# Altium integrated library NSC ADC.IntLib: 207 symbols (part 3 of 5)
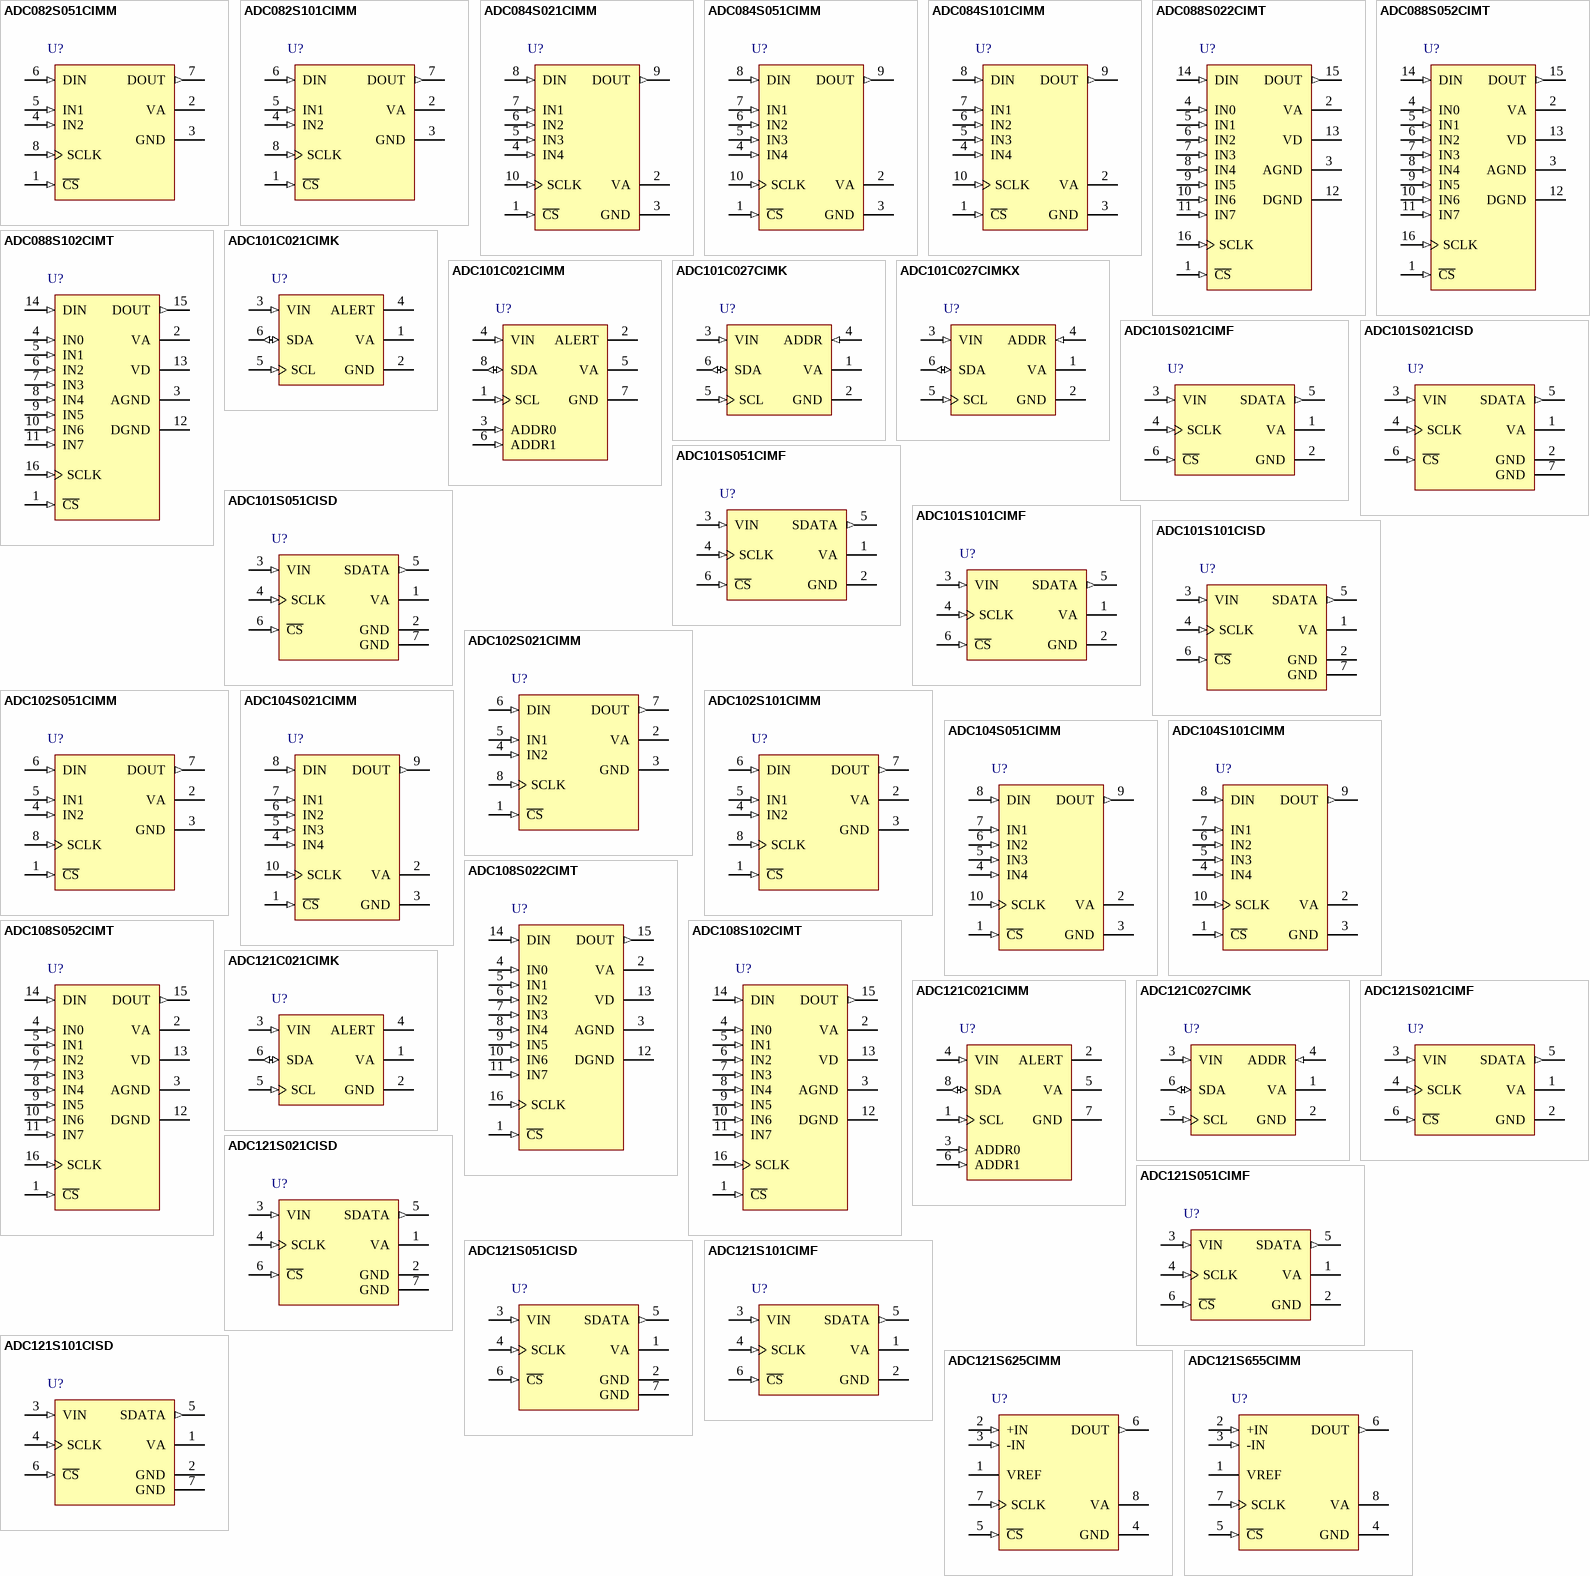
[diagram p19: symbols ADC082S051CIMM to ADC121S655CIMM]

## ADC088S022CIMT
designator U?
8-Channel, 50 kSPS to 200 kSPS, 8-Bit A/D Converter; PartNumber: ADC088S022CIMT; Manufacturer: National Semiconductor; CompType: ADC IC; PackageTopMarking: NSUZXYTT*88S022*CIMT; PowerWise: Y
footprint MTC16_N (TSOP, 16-Leads, Body 5x4.4mm, Pitch 0.65mm, IPC Medium Density)
footprint MTC16_L (TSOP, 16-Leads, Body 5x4.4mm, Pitch 0.65mm, IPC High Density)
footprint MTC16_M (TSOP, 16-Leads, Body 5x4.4mm, Pitch 0.65mm, IPC Low Density)
pins: 1 ~{CS} (in), 2 VA (power), 3 AGND (power), 4 IN0 (in), 5 IN1 (in), 6 IN2 (in), 7 IN3 (in), 8 IN4 (in), 9 IN5 (in), 10 IN6 (in), 11 IN7 (in), 12 DGND (power), 13 VD (power), 14 DIN (in), 15 DOUT (out), 16 SCLK (in)

## ADC088S052CIMT
designator U?
8-Channel, 200 kSPS to 500 kSPS, 8-Bit A/D Converter; PartNumber: ADC088S052CIMT; Manufacturer: National Semiconductor; CompType: ADC IC; PackageTopMarking: NSUZXYTT*088S052*CIMT; PowerWise: Y
footprint MTC16_N (TSOP, 16-Leads, Body 5x4.4mm, Pitch 0.65mm, IPC Medium Density)
footprint MTC16_L (TSOP, 16-Leads, Body 5x4.4mm, Pitch 0.65mm, IPC High Density)
footprint MTC16_M (TSOP, 16-Leads, Body 5x4.4mm, Pitch 0.65mm, IPC Low Density)
pins: 1 ~{CS} (in), 2 VA (power), 3 AGND (power), 4 IN0 (in), 5 IN1 (in), 6 IN2 (in), 7 IN3 (in), 8 IN4 (in), 9 IN5 (in), 10 IN6 (in), 11 IN7 (in), 12 DGND (power), 13 VD (power), 14 DIN (in), 15 DOUT (out), 16 SCLK (in)

## ADC088S102CIMT
designator U?
8-Channel, 500 kSPS to 1 MSPS, 8-Bit A/D Converter; PartNumber: ADC088S102CIMT; Manufacturer: National Semiconductor; CompType: ADC IC; PackageTopMarking: NSUZXYTT*088S102*CIMT; PowerWise: Y
footprint MTC16_N (TSOP, 16-Leads, Body 5x4.4mm, Pitch 0.65mm, IPC Medium Density)
footprint MTC16_L (TSOP, 16-Leads, Body 5x4.4mm, Pitch 0.65mm, IPC High Density)
footprint MTC16_M (TSOP, 16-Leads, Body 5x4.4mm, Pitch 0.65mm, IPC Low Density)
pins: 1 ~{CS} (in), 2 VA (power), 3 AGND (power), 4 IN0 (in), 5 IN1 (in), 6 IN2 (in), 7 IN3 (in), 8 IN4 (in), 9 IN5 (in), 10 IN6 (in), 11 IN7 (in), 12 DGND (power), 13 VD (power), 14 DIN (in), 15 DOUT (out), 16 SCLK (in)

## ADC101C021CIMK
designator U?
I2C-Compatible, 10-Bit Analog-to-Digital Converter (ADC) with Alert Pin; PartNumber: ADC101C021CIMK; Manufacturer: National Semiconductor; CompType: ADC IC; PackageTopMarking: X33C*XTT; PowerWise: N
footprint MK06A_N (SOT23, 6-Leads, Body 3.0x1.7mm, Pitch 0.95mm, Lead Span 2.9mm, IPC Medium Density)
footprint MK06A_L (SOT23, 6-Leads, Body 3.0x1.7mm, Pitch 0.95mm, Lead Span 2.9mm, IPC High Density)
footprint MK06A_M (SOT23, 6-Leads, Body 3.0x1.7mm, Pitch 0.95mm, Lead Span 2.9mm, IPC Low Density)
pins: 1 VA (power), 2 GND (power), 3 VIN (in), 4 ALERT (oc), 5 SCL (in), 6 SDA (io)

## ADC101C021CIMM
designator U?
I2C-Compatible, 10-Bit Analog-to-Digital Converter (ADC) with Alert Pin; PartNumber: ADC101C021CIMM; Manufacturer: National Semiconductor; CompType: ADC IC; PackageTopMarking: ZXTT*X38C; PowerWise: N
footprint MUA08A_N (TSOP, 8-Leads, Body 3x3mm, Pitch 0.65mm, IPC Medium Density)
footprint MUA08A_L (TSOP, 8-Leads, Body 3x3mm, Pitch 0.65mm, IPC High Density)
footprint MUA08A_M (TSOP, 8-Leads, Body 3x3mm, Pitch 0.65mm, IPC Low Density)
pins: 1 SCL (in), 2 ALERT (oc), 3 ADDR0 (in), 4 VIN (in), 5 VA (power), 6 ADDR1 (in), 7 GND (power), 8 SDA (io)

## ADC101C027CIMK
designator U?
I2C-Compatible, 10-Bit Analog-to-Digital Converter (ADC) with Alert Function; PartNumber: ADC101C027CIMK; Manufacturer: National Semiconductor; CompType: ADC IC; PackageTopMarking: X32C*XTT; PowerWise: N
footprint MK06A_N (SOT23, 6-Leads, Body 3.0x1.7mm, Pitch 0.95mm, Lead Span 2.9mm, IPC Medium Density)
footprint MK06A_L (SOT23, 6-Leads, Body 3.0x1.7mm, Pitch 0.95mm, Lead Span 2.9mm, IPC High Density)
footprint MK06A_M (SOT23, 6-Leads, Body 3.0x1.7mm, Pitch 0.95mm, Lead Span 2.9mm, IPC Low Density)
pins: 1 VA (power), 2 GND (power), 3 VIN (in), 4 ADDR (in), 5 SCL (in), 6 SDA (io)

## ADC101C027CIMKX
designator U?
I2C-Compatible, 10-Bit Analog-to-Digital Converter (ADC) with Alert Function; PartNumber: ADC101C027CIMKX; Manufacturer: National Semiconductor; CompType: ADC IC; PackageTopMarking: X31C*XTT
footprint MK06A_N (SOT23, 6-Leads, Body 3.0x1.7mm, Pitch 0.95mm, Lead Span 2.9mm, IPC Medium Density)
footprint MK06A_L (SOT23, 6-Leads, Body 3.0x1.7mm, Pitch 0.95mm, Lead Span 2.9mm, IPC High Density)
footprint MK06A_M (SOT23, 6-Leads, Body 3.0x1.7mm, Pitch 0.95mm, Lead Span 2.9mm, IPC Low Density)
pins: 1 VA (power), 2 GND (power), 3 VIN (in), 4 ADDR (in), 5 SCL (in), 6 SDA (io)

## ADC101S021CIMF
designator U?
Single Channel, 50 to 200 ksps, 10-Bit A/D Converter; PartNumber: ADC101S021CIMF; Manufacturer: National Semiconductor; CompType: ADC IC; PackageTopMarking: X08C*XTT; PowerWise: Y
footprint MF06A_N (SOT23, 6-Leads, Body 2.9x1.6mm, Pitch 0.95mm, Lead Span 2.8mm, IPC Medium Density)
footprint MF06A_L (SOT23, 6-Leads, Body 2.9x1.6mm, Pitch 0.95mm, Lead Span 2.8mm, IPC High Density)
footprint MF06A_M (SOT23, 6-Leads, Body 2.9x1.6mm, Pitch 0.95mm, Lead Span 2.8mm, IPC Low Density)
pins: 1 VA (power), 2 GND (power), 3 VIN (in), 4 SCLK (in), 5 SDATA (out), 6 ~{CS} (in)

## ADC101S021CISD
designator U?
Single Channel, 50 to 200 ksps, 10-Bit A/D Converter; PartNumber: ADC101S021CISD; Manufacturer: National Semiconductor; CompType: ADC IC; PackageTopMarking: XTT*X8C; PowerWise: Y
footprint SDB06A (SON, 6-Leads, Body 2.2x2.5mm, Pitch 0.65mm, NSC Recommended (SC-70 Land))
pins: 1 VA (power), 2 GND (power), 3 VIN (in), 4 SCLK (in), 5 SDATA (out), 6 ~{CS} (in), 7 GND (power)

## ADC101S051CIMF
designator U?
Single Channel, 200 to 500 ksps, 10-Bit A/D Converter; PartNumber: ADC101S051CIMF; Manufacturer: National Semiconductor; CompType: ADC IC; PackageTopMarking: X14C*XTT; PowerWise: Y
footprint MF06A_N (SOT23, 6-Leads, Body 2.9x1.6mm, Pitch 0.95mm, Lead Span 2.8mm, IPC Medium Density)
footprint MF06A_L (SOT23, 6-Leads, Body 2.9x1.6mm, Pitch 0.95mm, Lead Span 2.8mm, IPC High Density)
footprint MF06A_M (SOT23, 6-Leads, Body 2.9x1.6mm, Pitch 0.95mm, Lead Span 2.8mm, IPC Low Density)
pins: 1 VA (power), 2 GND (power), 3 VIN (in), 4 SCLK (in), 5 SDATA (out), 6 ~{CS} (in)

## ADC101S051CISD
designator U?
Single Channel, 200 to 500 ksps, 10-Bit A/D Converter; PartNumber: ADC101S051CISD; Manufacturer: National Semiconductor; CompType: ADC IC; PackageTopMarking: XTT*X5C; PowerWise: Y
footprint SDB06A (SON, 6-Leads, Body 2.2x2.5mm, Pitch 0.65mm, NSC Recommended (SC-70 Land))
pins: 1 VA (power), 2 GND (power), 3 VIN (in), 4 SCLK (in), 5 SDATA (out), 6 ~{CS} (in), 7 GND (power)

## ADC101S101CIMF
designator U?
1MSPS, 10-Bit A/D Converter in SOT-23; PartNumber: ADC101S101CIMF; Manufacturer: National Semiconductor; CompType: ADC IC; PackageTopMarking: X02C*XTT; PowerWise: Y
footprint MF06A_N (SOT23, 6-Leads, Body 2.9x1.6mm, Pitch 0.95mm, Lead Span 2.8mm, IPC Medium Density)
footprint MF06A_L (SOT23, 6-Leads, Body 2.9x1.6mm, Pitch 0.95mm, Lead Span 2.8mm, IPC High Density)
footprint MF06A_M (SOT23, 6-Leads, Body 2.9x1.6mm, Pitch 0.95mm, Lead Span 2.8mm, IPC Low Density)
pins: 1 VA (power), 2 GND (power), 3 VIN (in), 4 SCLK (in), 5 SDATA (out), 6 ~{CS} (in)

## ADC101S101CISD
designator U?
1MSPS, 10-Bit A/D Converter in SOT-23; PartNumber: ADC101S101CISD; Manufacturer: National Semiconductor; CompType: ADC IC; PackageTopMarking: XTT*X2C; PowerWise: Y
footprint SDB06A (SON, 6-Leads, Body 2.2x2.5mm, Pitch 0.65mm, NSC Recommended (SC-70 Land))
pins: 1 VA (power), 2 GND (power), 3 VIN (in), 4 SCLK (in), 5 SDATA (out), 6 ~{CS} (in), 7 GND (power)

## ADC102S021CIMM
designator U?
2 Channel, 200 KSPS, 10-Bit A/D Converter; PartNumber: ADC102S021CIMM; Manufacturer: National Semiconductor; CompType: ADC IC; PackageTopMarking: ZXTT*X17C; PowerWise: Y
footprint MUA08A_N (TSOP, 8-Leads, Body 3x3mm, Pitch 0.65mm, IPC Medium Density)
footprint MUA08A_L (TSOP, 8-Leads, Body 3x3mm, Pitch 0.65mm, IPC High Density)
footprint MUA08A_M (TSOP, 8-Leads, Body 3x3mm, Pitch 0.65mm, IPC Low Density)
pins: 1 ~{CS} (in), 2 VA (power), 3 GND (power), 4 IN2 (in), 5 IN1 (in), 6 DIN (in), 7 DOUT (out), 8 SCLK (in)

## ADC102S051CIMM
designator U?
2 Channel, 500 kSPS, 10-Bit A/D Converter; PartNumber: ADC102S051CIMM; Manufacturer: National Semiconductor; CompType: ADC IC; PackageTopMarking: ZXTT*X05C; PowerWise: Y
footprint MUA08A_N (TSOP, 8-Leads, Body 3x3mm, Pitch 0.65mm, IPC Medium Density)
footprint MUA08A_L (TSOP, 8-Leads, Body 3x3mm, Pitch 0.65mm, IPC High Density)
footprint MUA08A_M (TSOP, 8-Leads, Body 3x3mm, Pitch 0.65mm, IPC Low Density)
pins: 1 ~{CS} (in), 2 VA (power), 3 GND (power), 4 IN2 (in), 5 IN1 (in), 6 DIN (in), 7 DOUT (out), 8 SCLK (in)

## ADC102S101CIMM
designator U?
2 Channel, 1 MSPS, 10-Bit A/D Converter; PartNumber: ADC102S101CIMM; Manufacturer: National Semiconductor; CompType: ADC IC; PackageTopMarking: ZXTT*X23C; PowerWise: Y
footprint MUA08A_N (TSOP, 8-Leads, Body 3x3mm, Pitch 0.65mm, IPC Medium Density)
footprint MUA08A_L (TSOP, 8-Leads, Body 3x3mm, Pitch 0.65mm, IPC High Density)
footprint MUA08A_M (TSOP, 8-Leads, Body 3x3mm, Pitch 0.65mm, IPC Low Density)
pins: 1 ~{CS} (in), 2 VA (power), 3 GND (power), 4 IN2 (in), 5 IN1 (in), 6 DIN (in), 7 DOUT (out), 8 SCLK (in)

## ADC104S021CIMM
designator U?
4 Channel 200 kSPS, 10-Bit A/D Converter; PartNumber: ADC104S021CIMM; Manufacturer: National Semiconductor; CompType: ADC IC; PackageTopMarking: ZXTT*X20C; PowerWise: Y
footprint MUB10A_N (TSSOP, 10-Leads, Body 3x3mm, Pitch 0.5mm, IPC Medium Density)
footprint MUB10A_L (TSSOP, 10-Leads, Body 3x3mm, Pitch 0.5mm, IPC High Density)
footprint MUB10A_M (TSSOP, 10-Leads, Body 3x3mm, Pitch 0.5mm, IPC Low Density)
pins: 1 ~{CS} (in), 2 VA (power), 3 GND (power), 4 IN4 (in), 5 IN3 (in), 6 IN2 (in), 7 IN1 (in), 8 DIN (in), 9 DOUT (out), 10 SCLK (in)

## ADC104S051CIMM
designator U?
4 Channel 500 kSPS, 10-Bit A/D Converter; PartNumber: ADC104S051CIMM; Manufacturer: National Semiconductor; CompType: ADC IC; PackageTopMarking: ZXTT*X11C; PowerWise: Y
footprint MUB10A_N (TSSOP, 10-Leads, Body 3x3mm, Pitch 0.5mm, IPC Medium Density)
footprint MUB10A_L (TSSOP, 10-Leads, Body 3x3mm, Pitch 0.5mm, IPC High Density)
footprint MUB10A_M (TSSOP, 10-Leads, Body 3x3mm, Pitch 0.5mm, IPC Low Density)
pins: 1 ~{CS} (in), 2 VA (power), 3 GND (power), 4 IN4 (in), 5 IN3 (in), 6 IN2 (in), 7 IN1 (in), 8 DIN (in), 9 DOUT (out), 10 SCLK (in)

## ADC104S101CIMM
designator U?
4 Channel 1 MSPS, 10-Bit A/D Converter; PartNumber: ADC104S101CIMM; Manufacturer: National Semiconductor; CompType: ADC IC; PackageTopMarking: ZXTT*X26C; PowerWise: Y
footprint MUB10A_N (TSSOP, 10-Leads, Body 3x3mm, Pitch 0.5mm, IPC Medium Density)
footprint MUB10A_L (TSSOP, 10-Leads, Body 3x3mm, Pitch 0.5mm, IPC High Density)
footprint MUB10A_M (TSSOP, 10-Leads, Body 3x3mm, Pitch 0.5mm, IPC Low Density)
pins: 1 ~{CS} (in), 2 VA (power), 3 GND (power), 4 IN4 (in), 5 IN3 (in), 6 IN2 (in), 7 IN1 (in), 8 DIN (in), 9 DOUT (out), 10 SCLK (in)

## ADC108S022CIMT
designator U?
8-Channel, 50 kSPS to 200 kSPS, 10-Bit A/D Converter; PartNumber: ADC108S022CIMT; Manufacturer: National Semiconductor; CompType: ADC IC; PackageTopMarking: NSUZXYTT*108S022*CIMT; PowerWise: Y
footprint MTC16_N (TSOP, 16-Leads, Body 5x4.4mm, Pitch 0.65mm, IPC Medium Density)
footprint MTC16_L (TSOP, 16-Leads, Body 5x4.4mm, Pitch 0.65mm, IPC High Density)
footprint MTC16_M (TSOP, 16-Leads, Body 5x4.4mm, Pitch 0.65mm, IPC Low Density)
pins: 1 ~{CS} (in), 2 VA (power), 3 AGND (power), 4 IN0 (in), 5 IN1 (in), 6 IN2 (in), 7 IN3 (in), 8 IN4 (in), 9 IN5 (in), 10 IN6 (in), 11 IN7 (in), 12 DGND (power), 13 VD (power), 14 DIN (in), 15 DOUT (out), 16 SCLK (in)

## ADC108S052CIMT
designator U?
8-Channel, 200 kSPS to 500 kSPS, 10-Bit A/D Converter; PartNumber: ADC108S052CIMT; Manufacturer: National Semiconductor; CompType: ADC IC; PackageTopMarking: NSUZXYTT*108S052*CIMT; PowerWise: Y
footprint MTC16_N (TSOP, 16-Leads, Body 5x4.4mm, Pitch 0.65mm, IPC Medium Density)
footprint MTC16_L (TSOP, 16-Leads, Body 5x4.4mm, Pitch 0.65mm, IPC High Density)
footprint MTC16_M (TSOP, 16-Leads, Body 5x4.4mm, Pitch 0.65mm, IPC Low Density)
pins: 1 ~{CS} (in), 2 VA (power), 3 AGND (power), 4 IN0 (in), 5 IN1 (in), 6 IN2 (in), 7 IN3 (in), 8 IN4 (in), 9 IN5 (in), 10 IN6 (in), 11 IN7 (in), 12 DGND (power), 13 VD (power), 14 DIN (in), 15 DOUT (out), 16 SCLK (in)

## ADC108S102CIMT
designator U?
8-Channel, 500 kSPS to 1 MSPS, 10-Bit A/D Converter; PartNumber: ADC108S102CIMT; Manufacturer: National Semiconductor; CompType: ADC IC; PackageTopMarking: NSUZXYTT*108S102*CIMT; PowerWise: Y
footprint MTC16_N (TSOP, 16-Leads, Body 5x4.4mm, Pitch 0.65mm, IPC Medium Density)
footprint MTC16_L (TSOP, 16-Leads, Body 5x4.4mm, Pitch 0.65mm, IPC High Density)
footprint MTC16_M (TSOP, 16-Leads, Body 5x4.4mm, Pitch 0.65mm, IPC Low Density)
pins: 1 ~{CS} (in), 2 VA (power), 3 AGND (power), 4 IN0 (in), 5 IN1 (in), 6 IN2 (in), 7 IN3 (in), 8 IN4 (in), 9 IN5 (in), 10 IN6 (in), 11 IN7 (in), 12 DGND (power), 13 VD (power), 14 DIN (in), 15 DOUT (out), 16 SCLK (in)

## ADC121C021CIMK
designator U?
I2C-Compatible, 12-Bit Analog-to-Digital Converter (ADC) with Alert Pin; PartNumber: ADC121C021CIMK; Manufacturer: National Semiconductor; CompType: ADC IC; PackageTopMarking: X30C*XTT; PowerWise: Y
footprint MK06A_N (SOT23, 6-Leads, Body 3.0x1.7mm, Pitch 0.95mm, Lead Span 2.9mm, IPC Medium Density)
footprint MK06A_L (SOT23, 6-Leads, Body 3.0x1.7mm, Pitch 0.95mm, Lead Span 2.9mm, IPC High Density)
footprint MK06A_M (SOT23, 6-Leads, Body 3.0x1.7mm, Pitch 0.95mm, Lead Span 2.9mm, IPC Low Density)
pins: 1 VA (power), 2 GND (power), 3 VIN (in), 4 ALERT (oc), 5 SCL (in), 6 SDA (io)

## ADC121C021CIMM
designator U?
I2C-Compatible, 12-Bit Analog-to-Digital Converter with Alert Pin; PartNumber: ADC121C021CIMM; Manufacturer: National Semiconductor; CompType: ADC IC; PackageTopMarking: ZXTT*X37C; PowerWise: Y
footprint MUA08A_N (TSOP, 8-Leads, Body 3x3mm, Pitch 0.65mm, IPC Medium Density)
footprint MUA08A_L (TSOP, 8-Leads, Body 3x3mm, Pitch 0.65mm, IPC High Density)
footprint MUA08A_M (TSOP, 8-Leads, Body 3x3mm, Pitch 0.65mm, IPC Low Density)
pins: 1 SCL (in), 2 ALERT (oc), 3 ADDR0 (in), 4 VIN (in), 5 VA (power), 6 ADDR1 (in), 7 GND (power), 8 SDA (io)

## ADC121C027CIMK
designator U?
I2C-Compatible, 12-Bit Analog-to-Digital Converter with Alert Function; PartNumber: ADC121C027CIMK; Manufacturer: National Semiconductor; CompType: ADC IC; PackageTopMarking: X31C*XTT; PowerWise: Y
footprint MK06A_N (SOT23, 6-Leads, Body 3.0x1.7mm, Pitch 0.95mm, Lead Span 2.9mm, IPC Medium Density)
footprint MK06A_L (SOT23, 6-Leads, Body 3.0x1.7mm, Pitch 0.95mm, Lead Span 2.9mm, IPC High Density)
footprint MK06A_M (SOT23, 6-Leads, Body 3.0x1.7mm, Pitch 0.95mm, Lead Span 2.9mm, IPC Low Density)
pins: 1 VA (power), 2 GND (power), 3 VIN (in), 4 ADDR (in), 5 SCL (in), 6 SDA (io)

## ADC121S021CIMF
designator U?
Single Channel, 50 to 200 ksps, 12-Bit A/D Converter; PartNumber: ADC121S021CIMF; Manufacturer: National Semiconductor; CompType: ADC IC; PackageTopMarking: X07C*XTT; PowerWise: Y
footprint MF06A_N (SOT23, 6-Leads, Body 2.9x1.6mm, Pitch 0.95mm, Lead Span 2.8mm, IPC Medium Density)
footprint MF06A_L (SOT23, 6-Leads, Body 2.9x1.6mm, Pitch 0.95mm, Lead Span 2.8mm, IPC High Density)
footprint MF06A_M (SOT23, 6-Leads, Body 2.9x1.6mm, Pitch 0.95mm, Lead Span 2.8mm, IPC Low Density)
pins: 1 VA (power), 2 GND (power), 3 VIN (in), 4 SCLK (in), 5 SDATA (out), 6 ~{CS} (in)

## ADC121S021CISD
designator U?
Single Channel, 50 to 200 ksps, 12-Bit A/D Converter; PartNumber: ADC121S021CISD; Manufacturer: National Semiconductor; CompType: ADC IC; PackageTopMarking: XTT*X7C; PowerWise: Y
footprint SDB06A (SON, 6-Leads, Body 2.2x2.5mm, Pitch 0.65mm, NSC Recommended (SC-70 Land))
pins: 1 VA (power), 2 GND (power), 3 VIN (in), 4 SCLK (in), 5 SDATA (out), 6 ~{CS} (in), 7 GND (power)

## ADC121S051CIMF
designator U?
Single Channel, 200 to 500 ksps, 12-Bit A/D Converter; PartNumber: ADC121S051CIMF; Manufacturer: National Semiconductor; CompType: ADC IC; PackageTopMarking: X13C*XTT; PowerWise: Y
footprint MF06A_N (SOT23, 6-Leads, Body 2.9x1.6mm, Pitch 0.95mm, Lead Span 2.8mm, IPC Medium Density)
footprint MF06A_L (SOT23, 6-Leads, Body 2.9x1.6mm, Pitch 0.95mm, Lead Span 2.8mm, IPC High Density)
footprint MF06A_M (SOT23, 6-Leads, Body 2.9x1.6mm, Pitch 0.95mm, Lead Span 2.8mm, IPC Low Density)
pins: 1 VA (power), 2 GND (power), 3 VIN (in), 4 SCLK (in), 5 SDATA (out), 6 ~{CS} (in)

## ADC121S051CISD
designator U?
Single Channel, 200 to 500 ksps, 12-Bit A/D Converter; PartNumber: ADC121S051CISD; Manufacturer: National Semiconductor; CompType: ADC IC; PackageTopMarking: XTT*X4C; PowerWise: Y
footprint SDB06A (SON, 6-Leads, Body 2.2x2.5mm, Pitch 0.65mm, NSC Recommended (SC-70 Land))
pins: 1 VA (power), 2 GND (power), 3 VIN (in), 4 SCLK (in), 5 SDATA (out), 6 ~{CS} (in), 7 GND (power)

## ADC121S101CIMF
designator U?
1MSPS, 12-Bit A/D Converter in SOT-23; PartNumber: ADC121S101CIMF; Manufacturer: National Semiconductor; CompType: ADC IC; PackageTopMarking: X01C*XTT; PowerWise: Y
footprint MF06A_N (SOT23, 6-Leads, Body 2.9x1.6mm, Pitch 0.95mm, Lead Span 2.8mm, IPC Medium Density)
footprint MF06A_L (SOT23, 6-Leads, Body 2.9x1.6mm, Pitch 0.95mm, Lead Span 2.8mm, IPC High Density)
footprint MF06A_M (SOT23, 6-Leads, Body 2.9x1.6mm, Pitch 0.95mm, Lead Span 2.8mm, IPC Low Density)
pins: 1 VA (power), 2 GND (power), 3 VIN (in), 4 SCLK (in), 5 SDATA (out), 6 ~{CS} (in)

## ADC121S101CISD
designator U?
1MSPS, 12-Bit A/D Converter in SOT-23; PartNumber: ADC121S101CISD; Manufacturer: National Semiconductor; CompType: ADC IC; PackageTopMarking: XTT*X1C; PowerWise: Y
footprint SDB06A (SON, 6-Leads, Body 2.2x2.5mm, Pitch 0.65mm, NSC Recommended (SC-70 Land))
pins: 1 VA (power), 2 GND (power), 3 VIN (in), 4 SCLK (in), 5 SDATA (out), 6 ~{CS} (in), 7 GND (power)

## ADC121S625CIMM
designator U?
12-Bit, 50 ksps to 200 ksps, Differential Input, Micro Power Sampling A/D Converter; PartNumber: ADC121S625CIMM; Manufacturer: National Semiconductor; CompType: ADC IC; PackageTopMarking: ZXTT*X0AC; PowerWise: N
footprint MUA08A_N (TSOP, 8-Leads, Body 3x3mm, Pitch 0.65mm, IPC Medium Density)
footprint MUA08A_L (TSOP, 8-Leads, Body 3x3mm, Pitch 0.65mm, IPC High Density)
footprint MUA08A_M (TSOP, 8-Leads, Body 3x3mm, Pitch 0.65mm, IPC Low Density)
pins: 1 VREF (power), 2 +IN (in), 3 -IN (in), 4 GND (power), 5 ~{CS} (in), 6 DOUT (out), 7 SCLK (in), 8 VA (power)

## ADC121S655CIMM
designator U?
12-Bit, 200 kSPS to 500 kSPS, Differential Input, Micro Power A/D Converter; PartNumber: ADC121S655CIMM; Manufacturer: National Semiconductor; CompType: ADC IC; PackageTopMarking: ZXTT*X2AC; PowerWise: N
footprint MUA08A_N (TSOP, 8-Leads, Body 3x3mm, Pitch 0.65mm, IPC Medium Density)
footprint MUA08A_L (TSOP, 8-Leads, Body 3x3mm, Pitch 0.65mm, IPC High Density)
footprint MUA08A_M (TSOP, 8-Leads, Body 3x3mm, Pitch 0.65mm, IPC Low Density)
pins: 1 VREF (power), 2 +IN (in), 3 -IN (in), 4 GND (power), 5 ~{CS} (in), 6 DOUT (out), 7 SCLK (in), 8 VA (power)

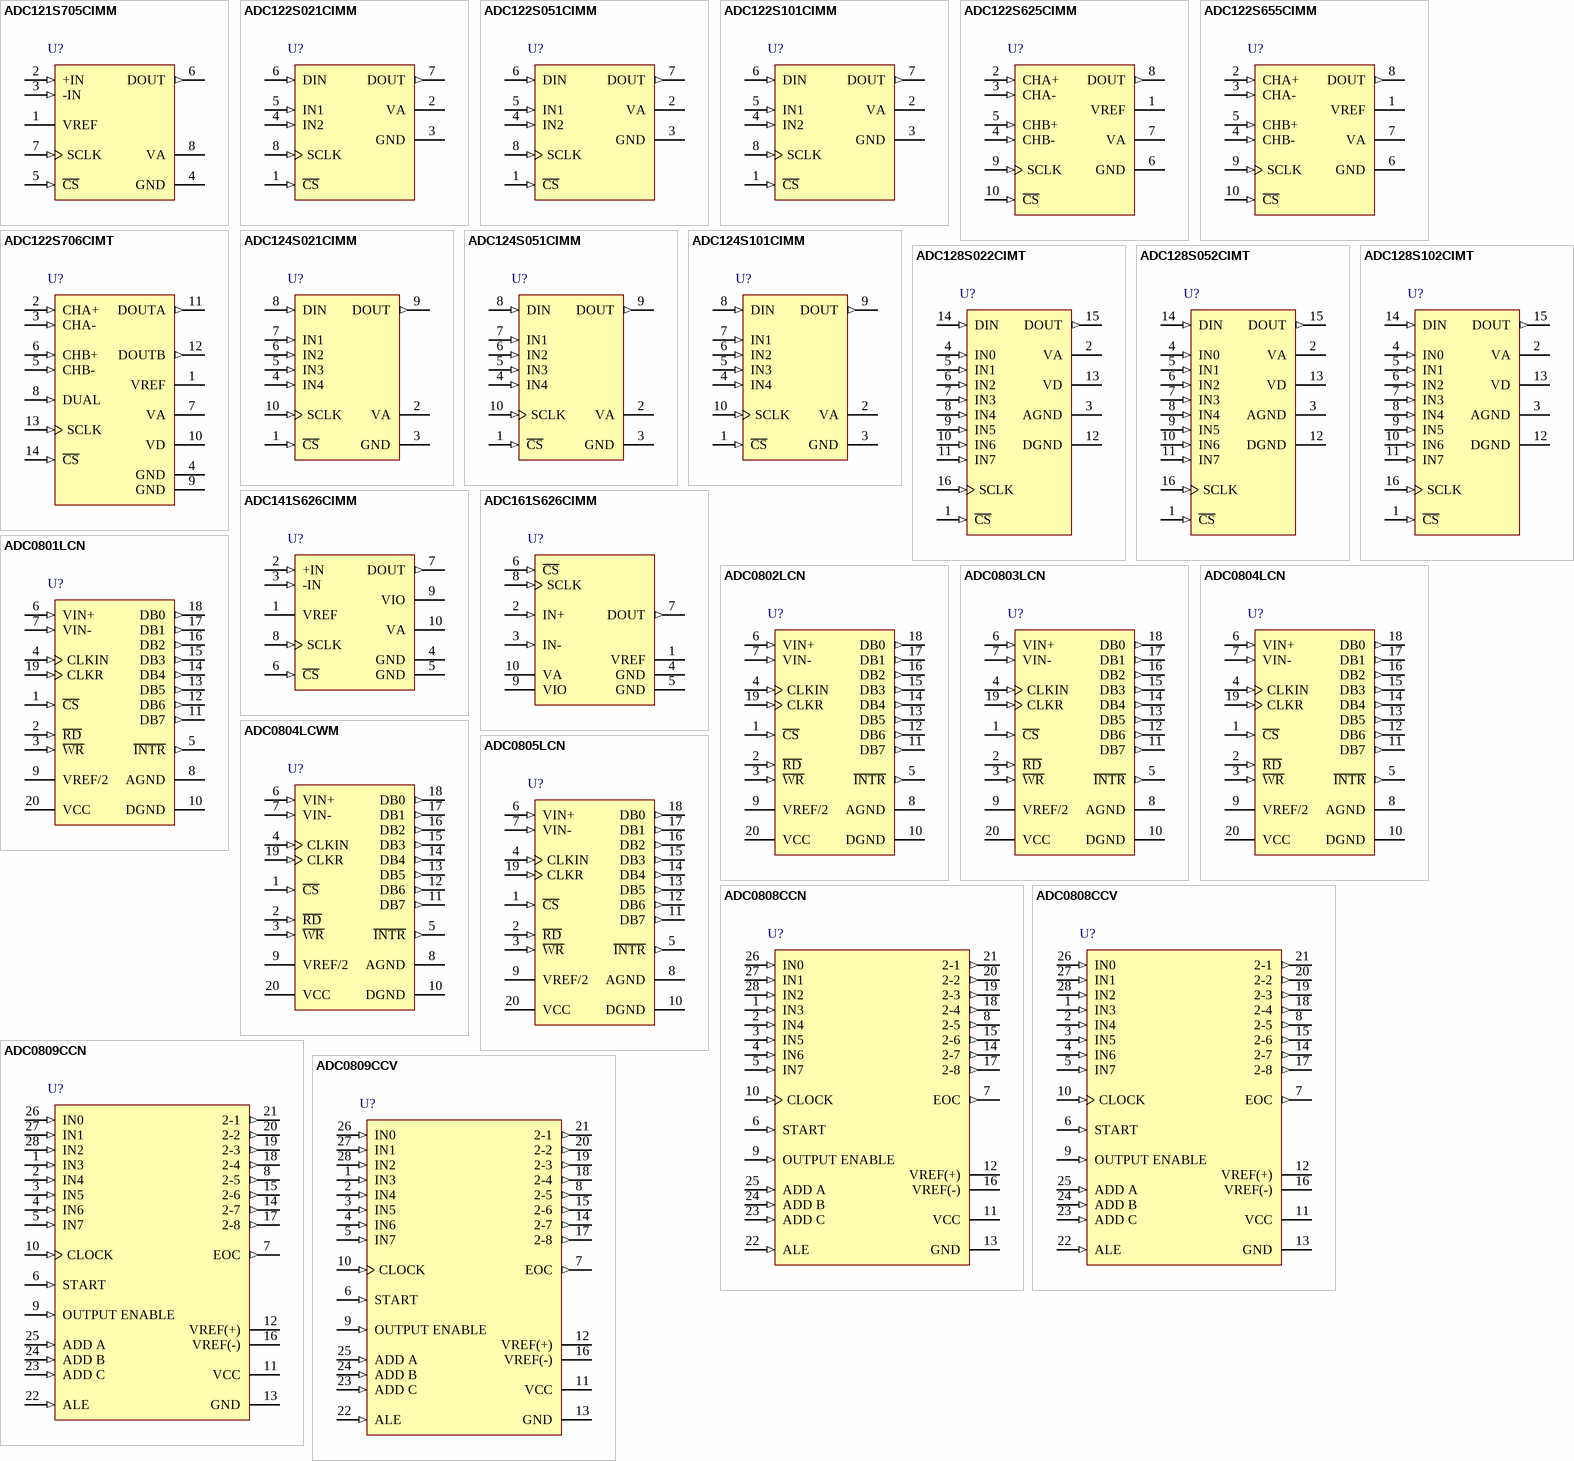
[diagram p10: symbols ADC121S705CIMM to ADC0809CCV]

## ADC121S705CIMM
designator U?
12-Bit, 500 kSPS to 1 MSPS, Differential Input, Micro Power A/D Converter; PartNumber: ADC121S705CIMM; Manufacturer: National Semiconductor; CompType: ADC IC; PackageTopMarking: ZXTT*X1AC; PowerWise: N
footprint MUA08A_N (TSOP, 8-Leads, Body 3x3mm, Pitch 0.65mm, IPC Medium Density)
footprint MUA08A_L (TSOP, 8-Leads, Body 3x3mm, Pitch 0.65mm, IPC High Density)
footprint MUA08A_M (TSOP, 8-Leads, Body 3x3mm, Pitch 0.65mm, IPC Low Density)
pins: 1 VREF (power), 2 +IN (in), 3 -IN (in), 4 GND (power), 5 ~{CS} (in), 6 DOUT (out), 7 SCLK (in), 8 VA (power)

## ADC122S021CIMM
designator U?
2 Channel, 200 KSPS 12-Bit A/D Converter; PartNumber: ADC122S021CIMM; Manufacturer: National Semiconductor; CompType: ADC IC; PackageTopMarking: ZXTT*X18C; PowerWise: Y
footprint MUA08A_N (TSOP, 8-Leads, Body 3x3mm, Pitch 0.65mm, IPC Medium Density)
footprint MUA08A_L (TSOP, 8-Leads, Body 3x3mm, Pitch 0.65mm, IPC High Density)
footprint MUA08A_M (TSOP, 8-Leads, Body 3x3mm, Pitch 0.65mm, IPC Low Density)
pins: 1 ~{CS} (in), 2 VA (power), 3 GND (power), 4 IN2 (in), 5 IN1 (in), 6 DIN (in), 7 DOUT (out), 8 SCLK (in)

## ADC122S051CIMM
designator U?
2 Channel, 500 kSPS 12-Bit A/D Converter; PartNumber: ADC122S051CIMM; Manufacturer: National Semiconductor; CompType: ADC IC; PackageTopMarking: ZXTT*X06C; PowerWise: Y
footprint MUA08A_N (TSOP, 8-Leads, Body 3x3mm, Pitch 0.65mm, IPC Medium Density)
footprint MUA08A_L (TSOP, 8-Leads, Body 3x3mm, Pitch 0.65mm, IPC High Density)
footprint MUA08A_M (TSOP, 8-Leads, Body 3x3mm, Pitch 0.65mm, IPC Low Density)
pins: 1 ~{CS} (in), 2 VA (power), 3 GND (power), 4 IN2 (in), 5 IN1 (in), 6 DIN (in), 7 DOUT (out), 8 SCLK (in)

## ADC122S101CIMM
designator U?
2 Channel, 1MSPS 12-Bit A/D Converter; PartNumber: ADC122S101CIMM; Manufacturer: National Semiconductor; CompType: ADC IC; PackageTopMarking: ZXTT*X24C; PowerWise: Y
footprint MUA08A_N (TSOP, 8-Leads, Body 3x3mm, Pitch 0.65mm, IPC Medium Density)
footprint MUA08A_L (TSOP, 8-Leads, Body 3x3mm, Pitch 0.65mm, IPC High Density)
footprint MUA08A_M (TSOP, 8-Leads, Body 3x3mm, Pitch 0.65mm, IPC Low Density)
pins: 1 ~{CS} (in), 2 VA (power), 3 GND (power), 4 IN2 (in), 5 IN1 (in), 6 DIN (in), 7 DOUT (out), 8 SCLK (in)

## ADC122S625CIMM
designator U?
Dual 12-Bit, 50 kSPS to 200 kSPS, Simultaneous Sampling A/D Converter; PartNumber: ADC122S625CIMM; Manufacturer: National Semiconductor; CompType: ADC IC; PackageTopMarking: ZXTT*X35C; PowerWise: N
footprint MUB10A_N (TSSOP, 10-Leads, Body 3x3mm, Pitch 0.5mm, IPC Medium Density)
footprint MUB10A_L (TSSOP, 10-Leads, Body 3x3mm, Pitch 0.5mm, IPC High Density)
footprint MUB10A_M (TSSOP, 10-Leads, Body 3x3mm, Pitch 0.5mm, IPC Low Density)
pins: 1 VREF (power), 2 CHA+ (in), 3 CHA- (in), 4 CHB- (in), 5 CHB+ (in), 6 GND (power), 7 VA (power), 8 DOUT (out), 9 SCLK (in), 10 ~{CS} (in)

## ADC122S655CIMM
designator U?
Dual 12-Bit, 200 kSPS to 500 kSPS, Simultaneous Sampling A/D Converter; PartNumber: ADC122S655CIMM; Manufacturer: National Semiconductor; CompType: ADC IC; PackageTopMarking: ZXTT*X96C; PowerWise: N
footprint MUB10A_N (TSSOP, 10-Leads, Body 3x3mm, Pitch 0.5mm, IPC Medium Density)
footprint MUB10A_L (TSSOP, 10-Leads, Body 3x3mm, Pitch 0.5mm, IPC High Density)
footprint MUB10A_M (TSSOP, 10-Leads, Body 3x3mm, Pitch 0.5mm, IPC Low Density)
pins: 1 VREF (power), 2 CHA+ (in), 3 CHA- (in), 4 CHB- (in), 5 CHB+ (in), 6 GND (power), 7 VA (power), 8 DOUT (out), 9 SCLK (in), 10 ~{CS} (in)

## ADC122S706CIMT
designator U?
Dual 12-Bit, 500 kSPS to 1 MSPS, Simultaneous Sampling A/D Converter; PartNumber: ADC122S706CIMT; Manufacturer: National Semiconductor; CompType: ADC IC; PackageTopMarking: NSUZXYTT*2S706*CIMT; PowerWise: N
footprint MTC14_N (TSOP, 14-Leads, Body 5x4.4mm, Pitch 0.65mm, IPC Medium Density)
footprint MTC14_L (TSOP, 14-Leads, Body 5x4.4mm, Pitch 0.65mm, IPC High Density)
footprint MTC14_M (TSOP, 14-Leads, Body 5x4.4mm, Pitch 0.65mm, IPC Low Density)
pins: 1 VREF (power), 2 CHA+ (in), 3 CHA- (in), 4 GND (power), 5 CHB- (in), 6 CHB+ (in), 7 VA (power), 8 DUAL (in), 9 GND (power), 10 VD (power), 11 DOUTA (out), 12 DOUTB (out), 13 SCLK (in), 14 ~{CS} (in)

## ADC124S021CIMM
designator U?
4 Channel, 200 kSPS, 12-Bit A/D Converter; PartNumber: ADC124S021CIMM; Manufacturer: National Semiconductor; CompType: ADC IC; PackageTopMarking: ZXTT*X21C; PowerWise: Y
footprint MUB10A_N (TSSOP, 10-Leads, Body 3x3mm, Pitch 0.5mm, IPC Medium Density)
footprint MUB10A_L (TSSOP, 10-Leads, Body 3x3mm, Pitch 0.5mm, IPC High Density)
footprint MUB10A_M (TSSOP, 10-Leads, Body 3x3mm, Pitch 0.5mm, IPC Low Density)
pins: 1 ~{CS} (in), 2 VA (power), 3 GND (power), 4 IN4 (in), 5 IN3 (in), 6 IN2 (in), 7 IN1 (in), 8 DIN (in), 9 DOUT (out), 10 SCLK (in)

## ADC124S051CIMM
designator U?
4 Channel, 500 kSPS, 12-Bit A/D Converter; PartNumber: ADC124S051CIMM; Manufacturer: National Semiconductor; CompType: ADC IC; PackageTopMarking: ZXTT*X12C; PowerWise: Y
footprint MUB10A_N (TSSOP, 10-Leads, Body 3x3mm, Pitch 0.5mm, IPC Medium Density)
footprint MUB10A_L (TSSOP, 10-Leads, Body 3x3mm, Pitch 0.5mm, IPC High Density)
footprint MUB10A_M (TSSOP, 10-Leads, Body 3x3mm, Pitch 0.5mm, IPC Low Density)
pins: 1 ~{CS} (in), 2 VA (power), 3 GND (power), 4 IN4 (in), 5 IN3 (in), 6 IN2 (in), 7 IN1 (in), 8 DIN (in), 9 DOUT (out), 10 SCLK (in)

## ADC124S101CIMM
designator U?
4 Channel, 1 MSPS, 12-Bit A/D Converter; PartNumber: ADC124S101CIMM; Manufacturer: National Semiconductor; CompType: ADC IC; PackageTopMarking: ZXTT*X27C; PowerWise: Y
footprint MUB10A_N (TSSOP, 10-Leads, Body 3x3mm, Pitch 0.5mm, IPC Medium Density)
footprint MUB10A_L (TSSOP, 10-Leads, Body 3x3mm, Pitch 0.5mm, IPC High Density)
footprint MUB10A_M (TSSOP, 10-Leads, Body 3x3mm, Pitch 0.5mm, IPC Low Density)
pins: 1 ~{CS} (in), 2 VA (power), 3 GND (power), 4 IN4 (in), 5 IN3 (in), 6 IN2 (in), 7 IN1 (in), 8 DIN (in), 9 DOUT (out), 10 SCLK (in)

## ADC128S022CIMT
designator U?
8-Channel, 50 kSPS to 200 kSPS, 12-Bit A/D Converter; PartNumber: ADC128S022CIMT; Manufacturer: National Semiconductor; CompType: ADC IC; PackageTopMarking: NSUZXYTT*128S022*CIMT; PowerWise: Y
footprint MTC16_N (TSOP, 16-Leads, Body 5x4.4mm, Pitch 0.65mm, IPC Medium Density)
footprint MTC16_L (TSOP, 16-Leads, Body 5x4.4mm, Pitch 0.65mm, IPC High Density)
footprint MTC16_M (TSOP, 16-Leads, Body 5x4.4mm, Pitch 0.65mm, IPC Low Density)
pins: 1 ~{CS} (in), 2 VA (power), 3 AGND (power), 4 IN0 (in), 5 IN1 (in), 6 IN2 (in), 7 IN3 (in), 8 IN4 (in), 9 IN5 (in), 10 IN6 (in), 11 IN7 (in), 12 DGND (power), 13 VD (power), 14 DIN (in), 15 DOUT (out), 16 SCLK (in)

## ADC128S052CIMT
designator U?
8-Channel, 200 kSPS to 500 kSPS, 12-Bit A/D Converter; PartNumber: ADC128S052CIMT; Manufacturer: National Semiconductor; CompType: ADC IC; PackageTopMarking: NSUZXYTT*128S052*CIMT; PowerWise: Y
footprint MTC16_N (TSOP, 16-Leads, Body 5x4.4mm, Pitch 0.65mm, IPC Medium Density)
footprint MTC16_L (TSOP, 16-Leads, Body 5x4.4mm, Pitch 0.65mm, IPC High Density)
footprint MTC16_M (TSOP, 16-Leads, Body 5x4.4mm, Pitch 0.65mm, IPC Low Density)
pins: 1 ~{CS} (in), 2 VA (power), 3 AGND (power), 4 IN0 (in), 5 IN1 (in), 6 IN2 (in), 7 IN3 (in), 8 IN4 (in), 9 IN5 (in), 10 IN6 (in), 11 IN7 (in), 12 DGND (power), 13 VD (power), 14 DIN (in), 15 DOUT (out), 16 SCLK (in)

## ADC128S102CIMT
designator U?
8-Channel, 500 kSPS to 1 MSPS, 12-Bit A/D Converter; PartNumber: ADC128S102CIMT; Manufacturer: National Semiconductor; CompType: ADC IC; PackageTopMarking: NSUZXYTT*128S102*CIMT; PowerWise: Y
footprint MTC16_N (TSOP, 16-Leads, Body 5x4.4mm, Pitch 0.65mm, IPC Medium Density)
footprint MTC16_L (TSOP, 16-Leads, Body 5x4.4mm, Pitch 0.65mm, IPC High Density)
footprint MTC16_M (TSOP, 16-Leads, Body 5x4.4mm, Pitch 0.65mm, IPC Low Density)
pins: 1 ~{CS} (in), 2 VA (power), 3 AGND (power), 4 IN0 (in), 5 IN1 (in), 6 IN2 (in), 7 IN3 (in), 8 IN4 (in), 9 IN5 (in), 10 IN6 (in), 11 IN7 (in), 12 DGND (power), 13 VD (power), 14 DIN (in), 15 DOUT (out), 16 SCLK (in)

## ADC141S626CIMM
designator U?
14-Bit, 50 kSPS to 250 kSPS, Differential Input, Micro Power A/D Converter; PartNumber: ADC141S626CIMM; Manufacturer: National Semiconductor; CompType: ADC IC; PackageTopMarking: ZXTT*X94C; PowerWise: Y
footprint MUB10A_N (TSSOP, 10-Leads, Body 3x3mm, Pitch 0.5mm, IPC Medium Density)
footprint MUB10A_L (TSSOP, 10-Leads, Body 3x3mm, Pitch 0.5mm, IPC High Density)
footprint MUB10A_M (TSSOP, 10-Leads, Body 3x3mm, Pitch 0.5mm, IPC Low Density)
pins: 1 VREF (power), 2 +IN (in), 3 -IN (in), 4 GND (power), 5 GND (power), 6 ~{CS} (in), 7 DOUT (out), 8 SCLK (in), 9 VIO (power), 10 VA (power)

## ADC161S626CIMM
designator U?
16-Bit, 50 to 250 kSPS, Differential Input, MicroPower ADC; PartNumber: ADC161S626CIMM; Manufacturer: National Semiconductor; CompType: ADC IC; PackageTopMarking: ZXTT*X98C; PowerWise: Y
footprint MUB10A_N (TSSOP, 10-Leads, Body 3x3mm, Pitch 0.5mm, IPC Medium Density)
footprint MUB10A_L (TSSOP, 10-Leads, Body 3x3mm, Pitch 0.5mm, IPC High Density)
footprint MUB10A_M (TSSOP, 10-Leads, Body 3x3mm, Pitch 0.5mm, IPC Low Density)
pins: 1 VREF (power), 2 IN+ (in), 3 IN- (in), 4 GND (power), 5 GND (power), 6 ~{CS} (in), 7 DOUT (out), 8 SCLK (in), 9 VIO, 10 VA

## ADC0801LCN
designator U?
8-Bit uP Compatible A/D Converters; PartNumber: ADC0801LCN; Manufacturer: National Semiconductor; CompType: ADC IC; PackageTopMarking: NSUZXYYTTE#*ADC0801LCN; PowerWise: N
footprint N20A (DIP, 20-Leads, Row Spacing 7.62mm, Pitch 2.54mm, Body 26.07x6.6mm)
pins: 1 ~{CS} (in), 2 ~{RD} (in), 3 ~{WR} (in), 4 CLKIN (in), 5 ~{INTR} (out), 6 VIN+ (in), 7 VIN- (in), 8 AGND (power), 9 VREF/2 (power), 10 DGND (power), 11 DB7 (out), 12 DB6 (out), 13 DB5 (out), 14 DB4 (out), 15 DB3 (out), 16 DB2 (out), 17 DB1 (out), 18 DB0 (out), 19 CLKR (in), 20 VCC (power)

## ADC0802LCN
designator U?
8-Bit uP Compatible A/D Converters; PartNumber: ADC0802LCN; Manufacturer: National Semiconductor; CompType: ADC IC; PackageTopMarking: NSUZXYYTTE#*ADC0802LCN; PowerWise: N
footprint N20A (DIP, 20-Leads, Row Spacing 7.62mm, Pitch 2.54mm, Body 26.07x6.6mm)
pins: 1 ~{CS} (in), 2 ~{RD} (in), 3 ~{WR} (in), 4 CLKIN (in), 5 ~{INTR} (out), 6 VIN+ (in), 7 VIN- (in), 8 AGND (power), 9 VREF/2 (power), 10 DGND (power), 11 DB7 (out), 12 DB6 (out), 13 DB5 (out), 14 DB4 (out), 15 DB3 (out), 16 DB2 (out), 17 DB1 (out), 18 DB0 (out), 19 CLKR (in), 20 VCC (power)

## ADC0803LCN
designator U?
8-Bit uP Compatible A/D Converters; PartNumber: ADC0803LCN; Manufacturer: National Semiconductor; CompType: ADC IC; PackageTopMarking: NSUZXYYTTE#*ADC0803LCN; PowerWise: N
footprint N20A (DIP, 20-Leads, Row Spacing 7.62mm, Pitch 2.54mm, Body 26.07x6.6mm)
pins: 1 ~{CS} (in), 2 ~{RD} (in), 3 ~{WR} (in), 4 CLKIN (in), 5 ~{INTR} (out), 6 VIN+ (in), 7 VIN- (in), 8 AGND (power), 9 VREF/2 (power), 10 DGND (power), 11 DB7 (out), 12 DB6 (out), 13 DB5 (out), 14 DB4 (out), 15 DB3 (out), 16 DB2 (out), 17 DB1 (out), 18 DB0 (out), 19 CLKR (in), 20 VCC (power)

## ADC0804LCN
designator U?
8-Bit uP Compatible A/D Converters; PartNumber: ADC0804LCN; Manufacturer: National Semiconductor; CompType: ADC IC; PackageTopMarking: NSUZXYYTTE#*ADC0804LCN; PowerWise: N
footprint N20A (DIP, 20-Leads, Row Spacing 7.62mm, Pitch 2.54mm, Body 26.07x6.6mm)
pins: 1 ~{CS} (in), 2 ~{RD} (in), 3 ~{WR} (in), 4 CLKIN (in), 5 ~{INTR} (out), 6 VIN+ (in), 7 VIN- (in), 8 AGND (power), 9 VREF/2 (power), 10 DGND (power), 11 DB7 (out), 12 DB6 (out), 13 DB5 (out), 14 DB4 (out), 15 DB3 (out), 16 DB2 (out), 17 DB1 (out), 18 DB0 (out), 19 CLKR (in), 20 VCC (power)

## ADC0804LCWM
designator U?
8-Bit uP Compatible A/D Converters; PartNumber: ADC0804LCWM; Manufacturer: National Semiconductor; CompType: ADC IC; PackageTopMarking: NSUZXYTT*ADC0804*LCWM; PowerWise: N
footprint M20B_N (SOIC, 20-Leads, Body 12.8x7.5mm, Pitch 1.27mm, IPC Medium Density)
footprint M20B_L (SOIC, 20-Leads, Body 12.8x7.5mm, Pitch 1.27mm, IPC High Density)
footprint M20B_M (SOIC, 20-Leads, Body 12.8x7.5mm, Pitch 1.27mm, IPC Low Density)
pins: 1 ~{CS} (in), 2 ~{RD} (in), 3 ~{WR} (in), 4 CLKIN (in), 5 ~{INTR} (out), 6 VIN+ (in), 7 VIN- (in), 8 AGND (power), 9 VREF/2 (power), 10 DGND (power), 11 DB7 (out), 12 DB6 (out), 13 DB5 (out), 14 DB4 (out), 15 DB3 (out), 16 DB2 (out), 17 DB1 (out), 18 DB0 (out), 19 CLKR (in), 20 VCC (power)

## ADC0805LCN
designator U?
8-Bit uP Compatible A/D Converters; PartNumber: ADC0805LCN; Manufacturer: National Semiconductor; CompType: ADC IC; PackageTopMarking: NSUZXYYTTE#*ADC0805LCN
footprint N20A (DIP, 20-Leads, Row Spacing 7.62mm, Pitch 2.54mm, Body 26.07x6.6mm)
pins: 1 ~{CS} (in), 2 ~{RD} (in), 3 ~{WR} (in), 4 CLKIN (in), 5 ~{INTR} (out), 6 VIN+ (in), 7 VIN- (in), 8 AGND (power), 9 VREF/2 (power), 10 DGND (power), 11 DB7 (out), 12 DB6 (out), 13 DB5 (out), 14 DB4 (out), 15 DB3 (out), 16 DB2 (out), 17 DB1 (out), 18 DB0 (out), 19 CLKR (in), 20 VCC (power)

## ADC0808CCN
designator U?
8-bit Microprocessor Compatible A/D Converters With 8-Channel Multiplexer; PartNumber: ADC0808CCN; Manufacturer: National Semiconductor; CompType: ADC IC; PackageTopMarking: NSUZXYYTTE#*ADC0808CCN; PowerWise: N
footprint NA28E (DIP, 28-Leads, Row Spacing 15.24mm, Pitch 2.54mm, Body 36.83x13.72mm)
pins: 1 IN3 (in), 2 IN4 (in), 3 IN5 (in), 4 IN6 (in), 5 IN7 (in), 6 START (in), 7 EOC (out), 8 2-5 (out), 9 OUTPUT ENABLE (in), 10 CLOCK (in), 11 VCC (power), 12 VREF(+) (power), 13 GND (power), 14 2-7 (out), 15 2-6 (out), 16 VREF(-) (power), 17 2-8 (out), 18 2-4 (out), 19 2-3 (out), 20 2-2 (out), 21 2-1 (out), 22 ALE (in), 23 ADD C (in), 24 ADD B (in), 25 ADD A (in), 26 IN0 (in), 27 IN1 (in), 28 IN2 (in)

## ADC0808CCV
designator U?
8-bit Microprocessor Compatible A/D Converters With 8-Channel Multiplexer; PartNumber: ADC0808CCV; Manufacturer: National Semiconductor; CompType: ADC IC; PackageTopMarking: NSUZXYYTT*ADC0808*CCV; PowerWise: N
footprint V28A_N (Leaded Chip Carrier, 28-Leads, Body 11.5x11.5mm, Pitch 1.27mm, IPC Medium Density)
footprint V28A_L (Leaded Chip Carrier, 28-Leads, Body 11.5x11.5mm, Pitch 1.27mm, IPC High Density)
footprint V28A_M (Leaded Chip Carrier, 28-Leads, Body 11.5x11.5mm, Pitch 1.27mm, IPC Low Density)
pins: 1 IN3 (in), 2 IN4 (in), 3 IN5 (in), 4 IN6 (in), 5 IN7 (in), 6 START (in), 7 EOC (out), 8 2-5 (out), 9 OUTPUT ENABLE (in), 10 CLOCK (in), 11 VCC (power), 12 VREF(+) (power), 13 GND (power), 14 2-7 (out), 15 2-6 (out), 16 VREF(-) (power), 17 2-8 (out), 18 2-4 (out), 19 2-3 (out), 20 2-2 (out), 21 2-1 (out), 22 ALE (in), 23 ADD C (in), 24 ADD B (in), 25 ADD A (in), 26 IN0 (in), 27 IN1 (in), 28 IN2 (in)

## ADC0809CCN
designator U?
8-bit Microprocessor Compatible A/D Converters With 8-Channel Multiplexer; PartNumber: ADC0809CCN; Manufacturer: National Semiconductor; CompType: ADC IC; PackageTopMarking: NSUZXYYTTE#*ADC0809CCN; PowerWise: N
footprint NA28E (DIP, 28-Leads, Row Spacing 15.24mm, Pitch 2.54mm, Body 36.83x13.72mm)
pins: 1 IN3 (in), 2 IN4 (in), 3 IN5 (in), 4 IN6 (in), 5 IN7 (in), 6 START (in), 7 EOC (out), 8 2-5 (out), 9 OUTPUT ENABLE (in), 10 CLOCK (in), 11 VCC (power), 12 VREF(+) (power), 13 GND (power), 14 2-7 (out), 15 2-6 (out), 16 VREF(-) (power), 17 2-8 (out), 18 2-4 (out), 19 2-3 (out), 20 2-2 (out), 21 2-1 (out), 22 ALE (in), 23 ADD C (in), 24 ADD B (in), 25 ADD A (in), 26 IN0 (in), 27 IN1 (in), 28 IN2 (in)

## ADC0809CCV
designator U?
8-bit Microprocessor Compatible A/D Converters With 8-Channel Multiplexer; PartNumber: ADC0809CCV; Manufacturer: National Semiconductor; CompType: ADC IC; PackageTopMarking: NSUZXYYTT*ADC0809*CCV; PowerWise: N
footprint V28A_N (Leaded Chip Carrier, 28-Leads, Body 11.5x11.5mm, Pitch 1.27mm, IPC Medium Density)
footprint V28A_L (Leaded Chip Carrier, 28-Leads, Body 11.5x11.5mm, Pitch 1.27mm, IPC High Density)
footprint V28A_M (Leaded Chip Carrier, 28-Leads, Body 11.5x11.5mm, Pitch 1.27mm, IPC Low Density)
pins: 1 IN3 (in), 2 IN4 (in), 3 IN5 (in), 4 IN6 (in), 5 IN7 (in), 6 START (in), 7 EOC (out), 8 2-5 (out), 9 OUTPUT ENABLE (in), 10 CLOCK (in), 11 VCC (power), 12 VREF(+) (power), 13 GND (power), 14 2-7 (out), 15 2-6 (out), 16 VREF(-) (power), 17 2-8 (out), 18 2-4 (out), 19 2-3 (out), 20 2-2 (out), 21 2-1 (out), 22 ALE (in), 23 ADD C (in), 24 ADD B (in), 25 ADD A (in), 26 IN0 (in), 27 IN1 (in), 28 IN2 (in)

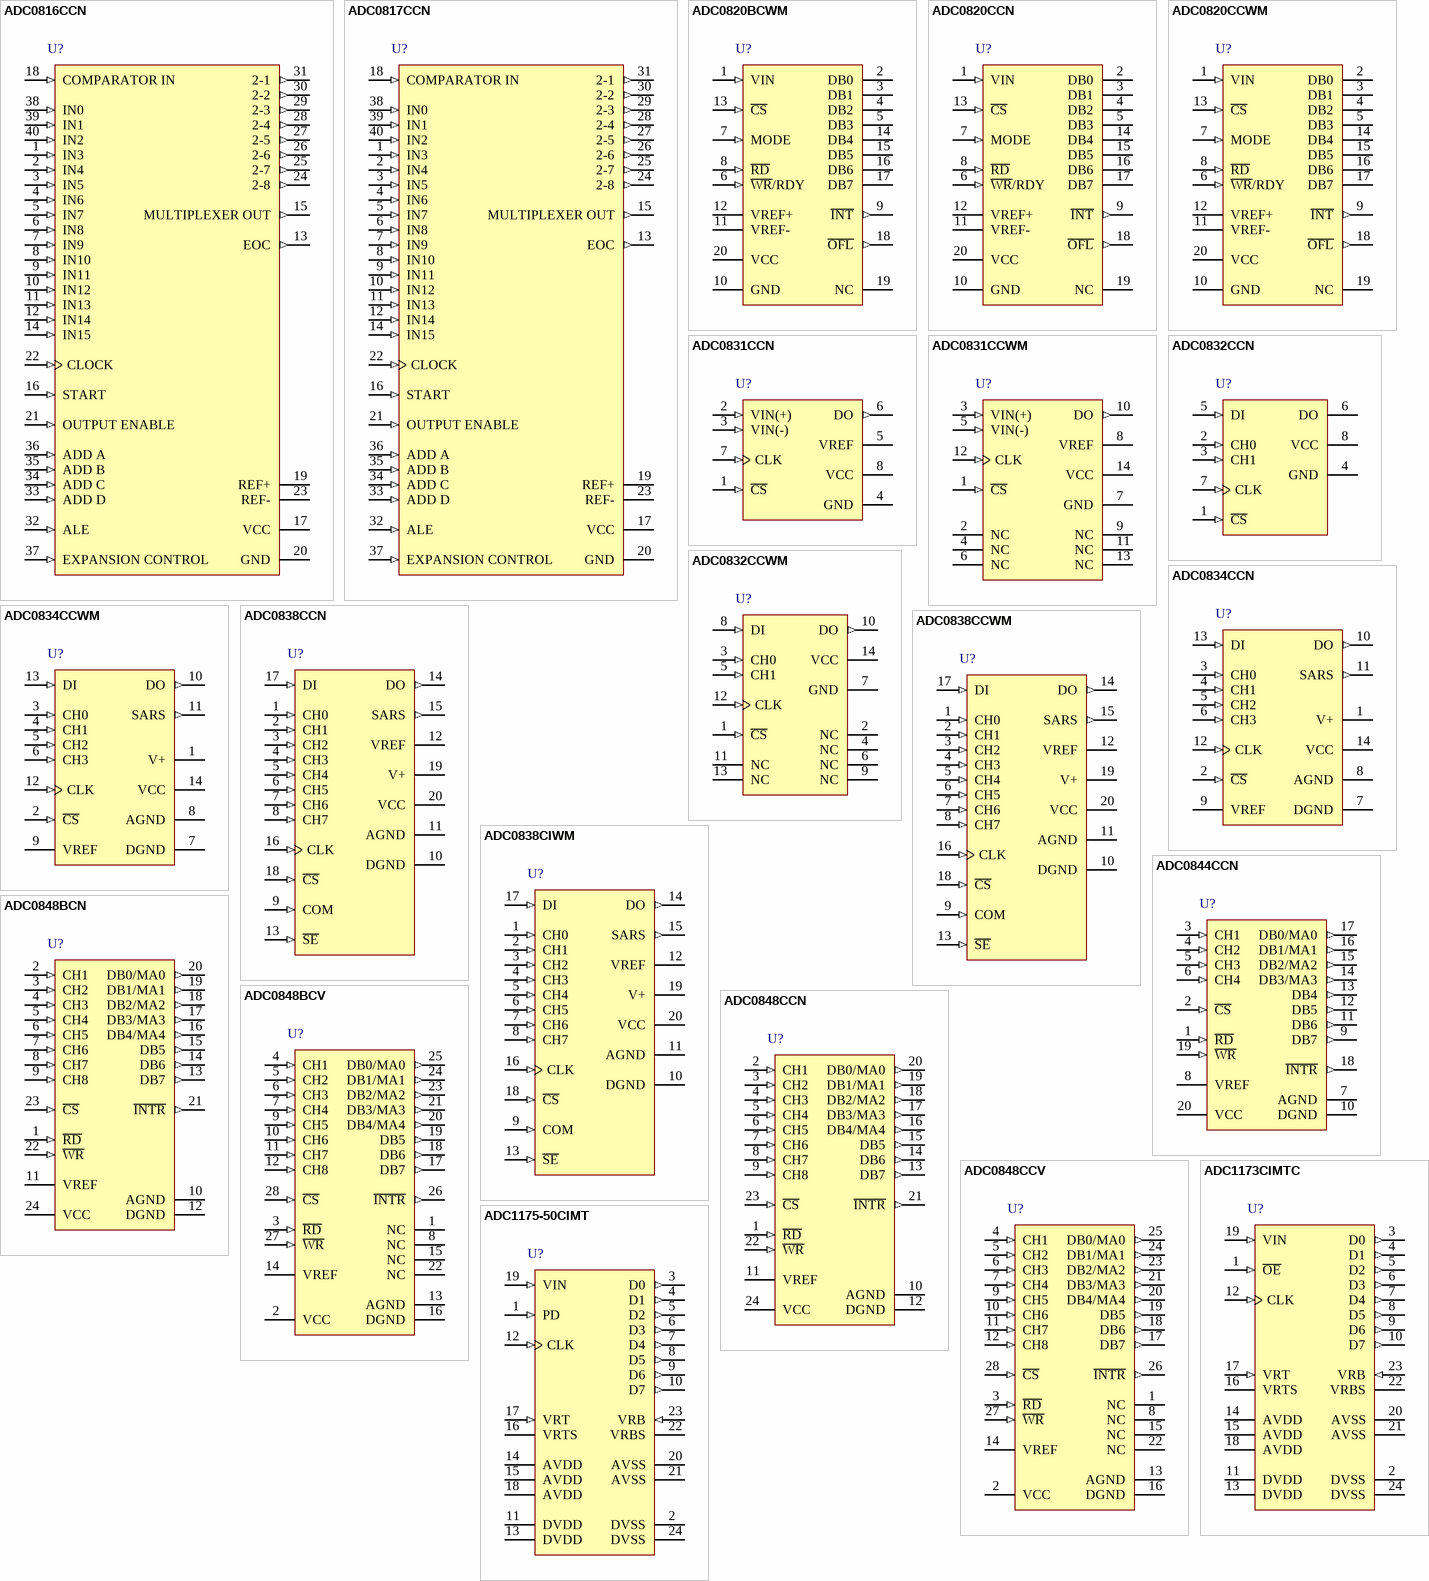
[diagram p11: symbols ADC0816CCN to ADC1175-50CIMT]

## ADC0816CCN
designator U?
8-Bit Microprocessor Compatible A/D Converter with 16-Channel Multiplexer; PartNumber: ADC0816CCN; Manufacturer: National Semiconductor; CompType: ADC IC; PackageTopMarking: NSUZXYYTTE#*ADC0816CCN; PowerWise: N
footprint N40A (DIP, 40-Leads, Row Spacing 15.24mm, Pitch 2.54mm, Body 52.24x13.97mm)
pins: 1 IN3 (in), 2 IN4 (in), 3 IN5 (in), 4 IN6 (in), 5 IN7 (in), 6 IN8 (in), 7 IN9 (in), 8 IN10 (in), 9 IN11 (in), 10 IN12 (in), 11 IN13 (in), 12 IN14 (in), 13 EOC (out), 14 IN15 (in), 15 MULTIPLEXER OUT (out), 16 START (in), 17 VCC (power), 18 COMPARATOR IN (in), 19 REF+ (power), 20 GND (power), 21 OUTPUT ENABLE (in), 22 CLOCK (in), 23 REF- (power), 24 2-8 (out), 25 2-7 (out), 26 2-6 (out), 27 2-5 (out), 28 2-4 (out), 29 2-3 (out), 30 2-2 (out), 31 2-1 (out), 32 ALE (in), 33 ADD D (in), 34 ADD C (in), 35 ADD B (in), 36 ADD A (in), 37 EXPANSION CONTROL (in), 38 IN0 (in), 39 IN1 (in), 40 IN2 (in)

## ADC0817CCN
designator U?
8-Bit Microprocessor Compatible A/D Converter with 16-Channel Multiplexer; PartNumber: ADC0817CCN; Manufacturer: National Semiconductor; CompType: ADC IC; PackageTopMarking: NSUZXYYTTE#*ADC0817CCN; PowerWise: N
footprint N40A (DIP, 40-Leads, Row Spacing 15.24mm, Pitch 2.54mm, Body 52.24x13.97mm)
pins: 1 IN3 (in), 2 IN4 (in), 3 IN5 (in), 4 IN6 (in), 5 IN7 (in), 6 IN8 (in), 7 IN9 (in), 8 IN10 (in), 9 IN11 (in), 10 IN12 (in), 11 IN13 (in), 12 IN14 (in), 13 EOC (out), 14 IN15 (in), 15 MULTIPLEXER OUT (out), 16 START (in), 17 VCC (power), 18 COMPARATOR IN (in), 19 REF+ (power), 20 GND (power), 21 OUTPUT ENABLE (in), 22 CLOCK (in), 23 REF- (power), 24 2-8 (out), 25 2-7 (out), 26 2-6 (out), 27 2-5 (out), 28 2-4 (out), 29 2-3 (out), 30 2-2 (out), 31 2-1 (out), 32 ALE (in), 33 ADD D (in), 34 ADD C (in), 35 ADD B (in), 36 ADD A (in), 37 EXPANSION CONTROL (in), 38 IN0 (in), 39 IN1 (in), 40 IN2 (in)

## ADC0820BCWM
designator U?
8-Bit High Speed uP Compatible A/D Converter with Track/Hold Function; PartNumber: ADC0820BCWM; Manufacturer: National Semiconductor; CompType: ADC IC; PackageTopMarking: NSUZXYTT*ADC0820*BCWM
footprint M20B_N (SOIC, 20-Leads, Body 12.8x7.5mm, Pitch 1.27mm, IPC Medium Density)
footprint M20B_L (SOIC, 20-Leads, Body 12.8x7.5mm, Pitch 1.27mm, IPC High Density)
footprint M20B_M (SOIC, 20-Leads, Body 12.8x7.5mm, Pitch 1.27mm, IPC Low Density)
pins: 1 VIN (in), 2 DB0 (hiz), 3 DB1 (hiz), 4 DB2 (hiz), 5 DB3 (hiz), 6 ~{WR}/RDY (in), 7 MODE (in), 8 ~{RD} (in), 9 ~{INT} (out), 10 GND (power), 11 VREF- (power), 12 VREF+ (power), 13 ~{CS} (in), 14 DB4 (hiz), 15 DB5 (hiz), 16 DB6 (hiz), 17 DB7 (hiz), 18 ~{OFL} (out), 19 NC, 20 VCC (power)

## ADC0820CCN
designator U?
8-Bit High Speed uP Compatible A/D Converter with Track/Hold Function; PartNumber: ADC0820CCN; Manufacturer: National Semiconductor; CompType: ADC IC; PackageTopMarking: NSUZXYYTTE#*ADC0820CCN; PowerWise: N
footprint N20A (DIP, 20-Leads, Row Spacing 7.62mm, Pitch 2.54mm, Body 26.07x6.6mm)
pins: 1 VIN (in), 2 DB0 (hiz), 3 DB1 (hiz), 4 DB2 (hiz), 5 DB3 (hiz), 6 ~{WR}/RDY (in), 7 MODE (in), 8 ~{RD} (in), 9 ~{INT} (out), 10 GND (power), 11 VREF- (power), 12 VREF+ (power), 13 ~{CS} (in), 14 DB4 (hiz), 15 DB5 (hiz), 16 DB6 (hiz), 17 DB7 (hiz), 18 ~{OFL} (out), 19 NC, 20 VCC (power)

## ADC0820CCWM
designator U?
8-Bit High Speed uP Compatible A/D Converter with Track/Hold Function; PartNumber: ADC0820CCWM; Manufacturer: National Semiconductor; CompType: ADC IC; PackageTopMarking: NSUZXYTT*ADC0820*CCWM; PowerWise: N
footprint M20B_N (SOIC, 20-Leads, Body 12.8x7.5mm, Pitch 1.27mm, IPC Medium Density)
footprint M20B_L (SOIC, 20-Leads, Body 12.8x7.5mm, Pitch 1.27mm, IPC High Density)
footprint M20B_M (SOIC, 20-Leads, Body 12.8x7.5mm, Pitch 1.27mm, IPC Low Density)
pins: 1 VIN (in), 2 DB0 (hiz), 3 DB1 (hiz), 4 DB2 (hiz), 5 DB3 (hiz), 6 ~{WR}/RDY (in), 7 MODE (in), 8 ~{RD} (in), 9 ~{INT} (out), 10 GND (power), 11 VREF- (power), 12 VREF+ (power), 13 ~{CS} (in), 14 DB4 (hiz), 15 DB5 (hiz), 16 DB6 (hiz), 17 DB7 (hiz), 18 ~{OFL} (out), 19 NC, 20 VCC (power)

## ADC0831CCN
designator U?
8-Bit Serial I/O A/D Converter with Multiplexer Option; PartNumber: ADC0831CCN; Manufacturer: National Semiconductor; CompType: ADC IC; PackageTopMarking: NSUZXYTT*ADC*0831CCN; PowerWise: N
footprint N08E (DIP, 8-Leads, Row Spacing 7.62mm, Pitch 2.54mm, Body 9.91x6.35mm)
pins: 1 ~{CS} (in), 2 VIN(+) (in), 3 VIN(-) (in), 4 GND (power), 5 VREF (power), 6 DO (out), 7 CLK (in), 8 VCC (power)

## ADC0831CCWM
designator U?
8-Bit Serial I/O A/D Converter with Multiplexer Option; PartNumber: ADC0831CCWM; Manufacturer: National Semiconductor; CompType: ADC IC; PackageTopMarking: NSUZXYTT*ADC0831*CCWM; PowerWise: N
footprint M14B_N (SOIC, 14-Leads, Body 9x7.5mm, Pitch 1.27mm, IPC Medium Density)
footprint M14B_L (SOIC, 14-Leads, Body 9x7.5mm, Pitch 1.27mm, IPC High Density)
footprint M14B_M (SOIC, 14-Leads, Body 9x7.5mm, Pitch 1.27mm, IPC Low Density)
pins: 1 ~{CS} (in), 2 NC, 3 VIN(+) (in), 4 NC, 5 VIN(-) (in), 6 NC, 7 GND (power), 8 VREF (power), 9 NC, 10 DO (out), 11 NC, 12 CLK (in), 13 NC, 14 VCC (power)

## ADC0832CCN
designator U?
8-Bit Serial I/O A/D Converter with Multiplexer Option; PartNumber: ADC0832CCN; Manufacturer: National Semiconductor; CompType: ADC IC; PackageTopMarking: NSUZXYTT*ADC*0832CCN; PowerWise: N
footprint N08E (DIP, 8-Leads, Row Spacing 7.62mm, Pitch 2.54mm, Body 9.91x6.35mm)
pins: 1 ~{CS} (in), 2 CH0 (in), 3 CH1 (in), 4 GND (power), 5 DI (in), 6 DO (hiz), 7 CLK (in), 8 VCC (power)

## ADC0832CCWM
designator U?
8-Bit Serial I/O A/D Converter with Multiplexer Option; PartNumber: ADC0832CCWM; Manufacturer: National Semiconductor; CompType: ADC IC; PackageTopMarking: NSUZXYTT*ADC0832*CCWM; PowerWise: N
footprint M14B_N (SOIC, 14-Leads, Body 9x7.5mm, Pitch 1.27mm, IPC Medium Density)
footprint M14B_L (SOIC, 14-Leads, Body 9x7.5mm, Pitch 1.27mm, IPC High Density)
footprint M14B_M (SOIC, 14-Leads, Body 9x7.5mm, Pitch 1.27mm, IPC Low Density)
pins: 1 ~{CS} (in), 2 NC, 3 CH0 (in), 4 NC, 5 CH1 (in), 6 NC, 7 GND (power), 8 DI (in), 9 NC, 10 DO (out), 11 NC, 12 CLK (in), 13 NC, 14 VCC (power)

## ADC0834CCN
designator U?
8-Bit Serial I/O A/D Converter with Multiplexer Option; PartNumber: ADC0834CCN; Manufacturer: National Semiconductor; CompType: ADC IC; PackageTopMarking: NSUZXYYTTE#*ADC0834CCN; PowerWise: N
footprint N14A (DIP, 14-Leads, Row Spacing 7.62mm, Pitch 2.54mm, Body 19.56x6.35mm)
pins: 1 V+ (power), 2 ~{CS} (in), 3 CH0 (in), 4 CH1 (in), 5 CH2 (in), 6 CH3 (in), 7 DGND (power), 8 AGND (power), 9 VREF (power), 10 DO (out), 11 SARS (out), 12 CLK (in), 13 DI (in), 14 VCC (power)

## ADC0834CCWM
designator U?
8-Bit Serial I/O A/D Converter with Multiplexer Option; PartNumber: ADC0834CCWM; Manufacturer: National Semiconductor; CompType: ADC IC; PackageTopMarking: NSUZXYTT*ADC0834*CCWM; PowerWise: N
footprint M14B_N (SOIC, 14-Leads, Body 9x7.5mm, Pitch 1.27mm, IPC Medium Density)
footprint M14B_L (SOIC, 14-Leads, Body 9x7.5mm, Pitch 1.27mm, IPC High Density)
footprint M14B_M (SOIC, 14-Leads, Body 9x7.5mm, Pitch 1.27mm, IPC Low Density)
pins: 1 V+ (power), 2 ~{CS} (in), 3 CH0 (in), 4 CH1 (in), 5 CH2 (in), 6 CH3 (in), 7 DGND (power), 8 AGND (power), 9 VREF (power), 10 DO (out), 11 SARS (out), 12 CLK (in), 13 DI (in), 14 VCC (power)

## ADC0838CCN
designator U?
8-Bit Serial I/O A/D Converter with Multiplexer Option; PartNumber: ADC0838CCN; Manufacturer: National Semiconductor; CompType: ADC IC; PackageTopMarking: NSUZXYYTTE#*ADC0838CCN; PowerWise: N
footprint N20A (DIP, 20-Leads, Row Spacing 7.62mm, Pitch 2.54mm, Body 26.07x6.6mm)
pins: 1 CH0 (in), 2 CH1 (in), 3 CH2 (in), 4 CH3 (in), 5 CH4 (in), 6 CH5 (in), 7 CH6 (in), 8 CH7 (in), 9 COM (in), 10 DGND (power), 11 AGND (power), 12 VREF (power), 13 ~{SE} (in), 14 DO (out), 15 SARS (out), 16 CLK (in), 17 DI (in), 18 ~{CS} (in), 19 V+ (power), 20 VCC (power)

## ADC0838CCWM
designator U?
8-Bit Serial I/O A/D Converter with Multiplexer Option; PartNumber: ADC0838CCWM; Manufacturer: National Semiconductor; CompType: ADC IC; PackageTopMarking: NSUZXYTT*ADC0838*CCWM; PowerWise: N
footprint M20B_N (SOIC, 20-Leads, Body 12.8x7.5mm, Pitch 1.27mm, IPC Medium Density)
footprint M20B_L (SOIC, 20-Leads, Body 12.8x7.5mm, Pitch 1.27mm, IPC High Density)
footprint M20B_M (SOIC, 20-Leads, Body 12.8x7.5mm, Pitch 1.27mm, IPC Low Density)
pins: 1 CH0 (in), 2 CH1 (in), 3 CH2 (in), 4 CH3 (in), 5 CH4 (in), 6 CH5 (in), 7 CH6 (in), 8 CH7 (in), 9 COM (in), 10 DGND (power), 11 AGND (power), 12 VREF (power), 13 ~{SE} (in), 14 DO (out), 15 SARS (out), 16 CLK (in), 17 DI (in), 18 ~{CS} (in), 19 V+ (power), 20 VCC (power)

## ADC0838CIWM
designator U?
8-Bit Serial I/O A/D Converter with Multiplexer Option; PartNumber: ADC0838CIWM; Manufacturer: National Semiconductor; CompType: ADC IC; PackageTopMarking: NSUZXYTT*ADC0838*CIWM; PowerWise: N
footprint M20B_N (SOIC, 20-Leads, Body 12.8x7.5mm, Pitch 1.27mm, IPC Medium Density)
footprint M20B_L (SOIC, 20-Leads, Body 12.8x7.5mm, Pitch 1.27mm, IPC High Density)
footprint M20B_M (SOIC, 20-Leads, Body 12.8x7.5mm, Pitch 1.27mm, IPC Low Density)
pins: 1 CH0 (in), 2 CH1 (in), 3 CH2 (in), 4 CH3 (in), 5 CH4 (in), 6 CH5 (in), 7 CH6 (in), 8 CH7 (in), 9 COM (in), 10 DGND (power), 11 AGND (power), 12 VREF (power), 13 ~{SE} (in), 14 DO (out), 15 SARS (out), 16 CLK (in), 17 DI (in), 18 ~{CS} (in), 19 V+ (power), 20 VCC (power)

## ADC0844CCN
designator U?
8-Bit Microprocessor Compatible A/D Converter with Multiplexer Option; PartNumber: ADC0844CCN; Manufacturer: National Semiconductor; CompType: ADC IC; PackageTopMarking: NSUZXYYTTE#*ADC0844CCN; PowerWise: N
footprint N20A (DIP, 20-Leads, Row Spacing 7.62mm, Pitch 2.54mm, Body 26.07x6.6mm)
pins: 1 ~{RD} (in), 2 ~{CS} (in), 3 CH1 (in), 4 CH2 (in), 5 CH3 (in), 6 CH4 (in), 7 AGND (power), 8 VREF (power), 9 DB7 (out), 10 DGND (power), 11 DB6 (out), 12 DB5 (out), 13 DB4 (out), 14 DB3/MA3 (out), 15 DB2/MA2 (out), 16 DB1/MA1 (out), 17 DB0/MA0 (out), 18 ~{INTR} (out), 19 ~{WR} (in), 20 VCC (power)

## ADC0848BCN
designator U?
8-Bit Microprocessor Compatible A/D Converter with Multiplexer Option; PartNumber: ADC0848BCN; Manufacturer: National Semiconductor; CompType: ADC IC; PackageTopMarking: NSUZXYYTTE#*ADC0848*BCN
footprint N24D (DIP, 24-Leads, Row Spacing 7.62mm, Pitch 2.54mm, Body 32x6.6mm)
pins: 1 ~{RD} (in), 2 CH1 (in), 3 CH2 (in), 4 CH3 (in), 5 CH4 (in), 6 CH5 (in), 7 CH6 (in), 8 CH7 (in), 9 CH8 (in), 10 AGND (power), 11 VREF (power), 12 DGND (power), 13 DB7 (out), 14 DB6 (out), 15 DB5 (out), 16 DB4/MA4 (out), 17 DB3/MA3 (out), 18 DB2/MA2 (out), 19 DB1/MA1 (out), 20 DB0/MA0 (out), 21 ~{INTR} (out), 22 ~{WR} (in), 23 ~{CS} (in), 24 VCC (power)

## ADC0848BCV
designator U?
8-Bit Microprocessor Compatible A/D Converter with Multiplexer Option; PartNumber: ADC0848BCV; Manufacturer: National Semiconductor; CompType: ADC IC; PackageTopMarking: NSUZXYYTT*ADC0848*BCV; PowerWise: N
footprint V28A_N (Leaded Chip Carrier, 28-Leads, Body 11.5x11.5mm, Pitch 1.27mm, IPC Medium Density)
footprint V28A_L (Leaded Chip Carrier, 28-Leads, Body 11.5x11.5mm, Pitch 1.27mm, IPC High Density)
footprint V28A_M (Leaded Chip Carrier, 28-Leads, Body 11.5x11.5mm, Pitch 1.27mm, IPC Low Density)
pins: 1 NC, 2 VCC (power), 3 ~{RD} (in), 4 CH1 (in), 5 CH2 (in), 6 CH3 (in), 7 CH4 (in), 8 NC, 9 CH5 (in), 10 CH6 (in), 11 CH7 (in), 12 CH8 (in), 13 AGND (power), 14 VREF (power), 15 NC, 16 DGND (power), 17 DB7 (out), 18 DB6 (out), 19 DB5 (out), 20 DB4/MA4 (out), 21 DB3/MA3 (out), 22 NC, 23 DB2/MA2 (out), 24 DB1/MA1 (out), 25 DB0/MA0 (out), 26 ~{INTR} (out), 27 ~{WR} (in), 28 ~{CS} (in)

## ADC0848CCN
designator U?
8-Bit Microprocessor Compatible A/D Converter with Multiplexer Option; PartNumber: ADC0848CCN; Manufacturer: National Semiconductor; CompType: ADC IC; PackageTopMarking: NSUZXYYTTE#*ADC0848CCN; PowerWise: N
footprint N24D (DIP, 24-Leads, Row Spacing 7.62mm, Pitch 2.54mm, Body 32x6.6mm)
pins: 1 ~{RD} (in), 2 CH1 (in), 3 CH2 (in), 4 CH3 (in), 5 CH4 (in), 6 CH5 (in), 7 CH6 (in), 8 CH7 (in), 9 CH8 (in), 10 AGND (power), 11 VREF (power), 12 DGND (power), 13 DB7 (out), 14 DB6 (out), 15 DB5 (out), 16 DB4/MA4 (out), 17 DB3/MA3 (out), 18 DB2/MA2 (out), 19 DB1/MA1 (out), 20 DB0/MA0 (out), 21 ~{INTR} (out), 22 ~{WR} (in), 23 ~{CS} (in), 24 VCC (power)

## ADC0848CCV
designator U?
8-Bit Microprocessor Compatible A/D Converter with Multiplexer Option; PartNumber: ADC0848CCV; Manufacturer: National Semiconductor; CompType: ADC IC; PackageTopMarking: NSUZXYYTT*ADC0848*CCV; PowerWise: N
footprint V28A_N (Leaded Chip Carrier, 28-Leads, Body 11.5x11.5mm, Pitch 1.27mm, IPC Medium Density)
footprint V28A_L (Leaded Chip Carrier, 28-Leads, Body 11.5x11.5mm, Pitch 1.27mm, IPC High Density)
footprint V28A_M (Leaded Chip Carrier, 28-Leads, Body 11.5x11.5mm, Pitch 1.27mm, IPC Low Density)
pins: 1 NC, 2 VCC (power), 3 ~{RD} (in), 4 CH1 (in), 5 CH2 (in), 6 CH3 (in), 7 CH4 (in), 8 NC, 9 CH5 (in), 10 CH6 (in), 11 CH7 (in), 12 CH8 (in), 13 AGND (power), 14 VREF (power), 15 NC, 16 DGND (power), 17 DB7 (out), 18 DB6 (out), 19 DB5 (out), 20 DB4/MA4 (out), 21 DB3/MA3 (out), 22 NC, 23 DB2/MA2 (out), 24 DB1/MA1 (out), 25 DB0/MA0 (out), 26 ~{INTR} (out), 27 ~{WR} (in), 28 ~{CS} (in)

## ADC1173CIMTC
designator U?
8-Bit, 3-Volt, 15MSPS, 33mW A/D Converter; PartNumber: ADC1173CIMTC; Manufacturer: National Semiconductor; CompType: ADC IC; PackageTopMarking: NSUZXYTT*ADC1173*CIMTC; PowerWise: N
footprint MTC24_N (TSOP, 24-Leads, Body 7.8x4.4mm, Pitch 0.65mm, IPC Medium Density)
footprint MTC24_L (TSOP, 24-Leads, Body 7.8x4.4mm, Pitch 0.65mm, IPC High Density)
footprint MTC24_M (TSOP, 24-Leads, Body 7.8x4.4mm, Pitch 0.65mm, IPC Low Density)
pins: 1 ~{OE} (in), 2 DVSS (power), 3 D0 (out), 4 D1 (out), 5 D2 (out), 6 D3 (out), 7 D4 (out), 8 D5 (out), 9 D6 (out), 10 D7 (out), 11 DVDD (power), 12 CLK (in), 13 DVDD (power), 14 AVDD (power), 15 AVDD (power), 16 VRTS, 17 VRT (in), 18 AVDD (power), 19 VIN (in), 20 AVSS (power), 21 AVSS (power), 22 VRBS, 23 VRB (in), 24 DVSS (power)

## ADC1175-50CIMT
designator U?
8-Bit, 50MSPS, 125mW A/D Converter; PartNumber: ADC1175-50CIMT; Manufacturer: National Semiconductor; CompType: ADC IC; PackageTopMarking: NSUZXYTT*ADC1175-50*CIMT
footprint MTC24_N (TSOP, 24-Leads, Body 7.8x4.4mm, Pitch 0.65mm, IPC Medium Density)
footprint MTC24_L (TSOP, 24-Leads, Body 7.8x4.4mm, Pitch 0.65mm, IPC High Density)
footprint MTC24_M (TSOP, 24-Leads, Body 7.8x4.4mm, Pitch 0.65mm, IPC Low Density)
pins: 1 PD (in), 2 DVSS (power), 3 D0 (out), 4 D1 (out), 5 D2 (out), 6 D3 (out), 7 D4 (out), 8 D5 (out), 9 D6 (out), 10 D7 (out), 11 DVDD (power), 12 CLK (in), 13 DVDD (power), 14 AVDD (power), 15 AVDD (power), 16 VRTS (power), 17 VRT (in), 18 AVDD (power), 19 VIN (in), 20 AVSS (power), 21 AVSS (power), 22 VRBS (power), 23 VRB (in), 24 DVSS (power)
